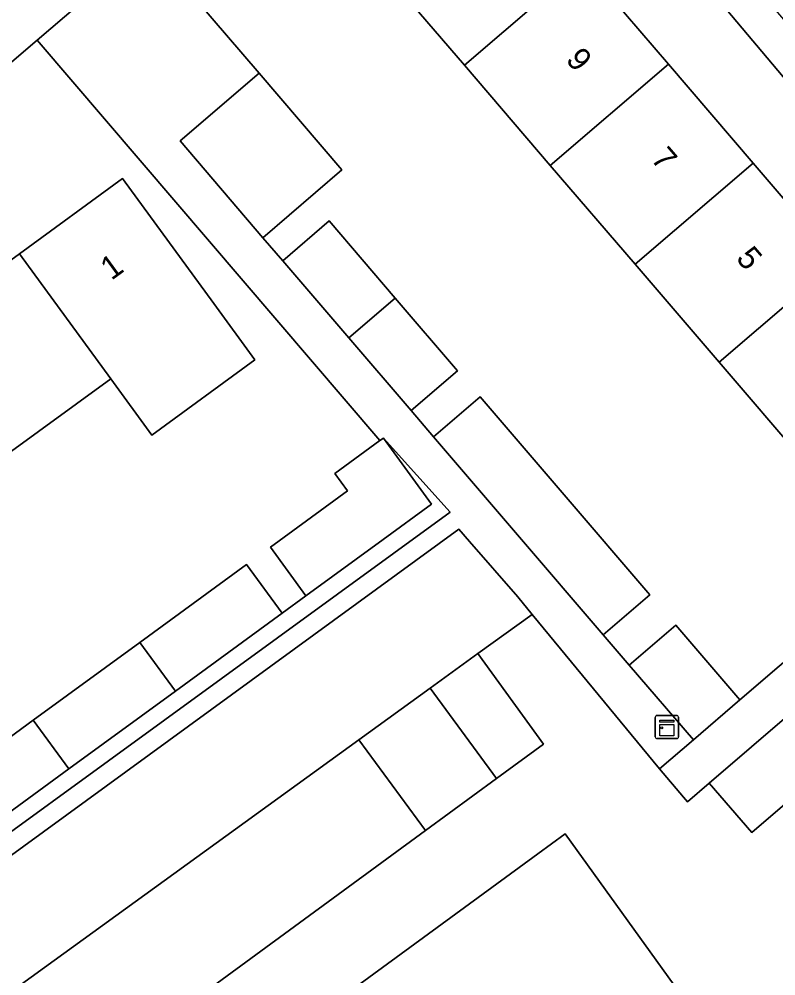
# Model space of a CAD drawing. Extents: x 159039 to 160102, y 381214 to 382524.
# Drawn here: x 159296.1 to 159328.7, y 381403.15 to 381444.39 of the extents above; entities that cross this region are included whole.
import ezdxf

# ---------------------------------------------------------------- set-up
doc = ezdxf.new("R2010")
doc.units = 0
for name, color, linetype in [('IMGEO_Erf', 7, 'Continuous'), ('IMGEO_Groenvoorziening', 7, 'Continuous'), ('IMGEO_Kast', 7, 'Continuous'), ('IMGEO_Pand', 7, 'Continuous'), ('IMGEO_Pand_nummerreeks', 7, 'Continuous'), ('IMGEO_Parkeervlak_halfverhard', 7, 'Continuous'), ('IMGEO_Parkeervlak_open', 7, 'Continuous'), ('IMGEO_Rijbaan_lokaal_halfverhard', 7, 'Continuous'), ('IMGEO_Rijbaan_lokaal_open', 7, 'Continuous'), ('IMGEO_Voetpad_open', 7, 'Continuous')]:
    doc.layers.add(name, color=color, linetype=linetype)

msp = doc.modelspace()

# ---------------------------------------------------------------- linework, layer by layer
at = {"layer": 'IMGEO_Erf'}
for points in [[(159313.561, 381454.682), (159312.01, 381456.432), (159309.4, 381454.198), (159301.691, 381447.601), (159306.439, 381442.052), (159310.009, 381437.884), (159306.602, 381434.965), (159307.456, 381433.968), (159309.461, 381435.686), (159312.306, 381432.365), (159314.99, 381429.232), (159312.985, 381427.514), (159313.954, 381426.383), (159315.959, 381428.101), (159319.576, 381423.877), (159323.265, 381419.571), (159321.261, 381417.854), (159322.385, 381416.542), (159324.389, 381418.259), (159327.147, 381415.04), (159333.82, 381420.762), (159329.941, 381425.29)], [(159329.941, 381425.29), (159326.252, 381429.596), (159322.634, 381433.82), (159318.981, 381438.084), (159315.282, 381442.402), (159311.688, 381446.598), (159316.78, 381450.96), (159320.374, 381446.765), (159324.073, 381442.447), (159327.725, 381438.182), (159331.344, 381433.958), (159335.033, 381429.652), (159338.909, 381425.126), (159341.458, 381427.312), (159335.852, 381433.782), (159319.724, 381452.954)], [(159293.47, 381411.804), (159296.711, 381414.169), (159301.301, 381417.519), (159305.896, 381420.873), (159307.426, 381418.777), (159308.458, 381419.53), (159306.928, 381421.626), (159310.249, 381424.05), (159309.701, 381424.801), (159311.645, 381426.22), (159296.875, 381443.481), (159263.262, 381414.719)]]:
    msp.add_lwpolyline(points, dxfattribs=at)
msp.add_lwpolyline([(159277.221, 381412.22), (159272.515, 381408.785), (159268.58, 381414.176), (159273.286, 381417.611), (159277.786, 381420.895), (159282.391, 381424.255), (159286.93, 381427.569), (159291.522, 381430.92), (159296.116, 381434.272), (159300.556, 381437.513), (159304.49, 381432.123), (159306.259, 381429.7), (159301.818, 381426.459), (159300.05, 381428.882), (159295.456, 381425.529), (159290.865, 381422.178), (159286.325, 381418.865), (159281.721, 381415.504)], close=True, dxfattribs=at)
at = {"layer": 'IMGEO_Groenvoorziening'}
for points in [[(159311.79, 381426.326), (159313.868, 381423.479), (159311.779, 381421.954), (159308.458, 381419.53), (159307.426, 381418.777), (159302.831, 381415.423), (159298.241, 381412.073), (159295, 381409.707), (159293.701, 381408.759), (159292.255, 381407.704), (159289.097, 381405.399), (159284.597, 381402.115), (159279.8, 381398.614), (159280.206, 381398.054), (159314.675, 381423.134)], [(159352.036, 381415.106), (159346.19, 381421.852), (159342.634, 381418.861), (159339.205, 381422.939), (159338.791, 381422.584), (159339.857, 381421.328), (159340.616, 381420.455), (159327.66, 381409.327), (159325.825, 381411.452), (159324.89, 381410.649), (159324.717, 381410.854), (159323.69, 381412.075), (159318.2, 381418.731), (159315.862, 381417.037), (159318.687, 381413.139), (159316.66, 381411.652), (159313.605, 381409.412), (159298.99, 381398.693), (159289.128, 381391.46), (159286.146, 381395.501), (159280.338, 381391.218), (159297.175, 381368.084)], [(159340.616, 381420.455), (159339.857, 381421.328), (159338.791, 381422.584), (159325.825, 381411.452), (159327.66, 381409.327)], [(159313.804, 381415.546), (159310.736, 381413.322), (159313.605, 381409.412), (159316.66, 381411.652)], [(159318.449, 381408.412), (159319.619, 381409.269), (159326.496, 381399.717), (159323.45, 381397.5), (159323.878, 381396.287), (159323.979, 381395.687), (159323.693, 381394.801), (159320.821, 381391.708), (159317.105, 381389.065), (159314.5, 381387.575), (159312.861, 381386.98), (159312, 381387.39), (159310.956, 381388.405), (159294.623, 381376.516), (159291.687, 381380.535), (159289.861, 381379.251), (159281.722, 381390.399), (159281.63, 381390.527), (159286.22, 381393.893), (159289.626, 381389.249), (159290.547, 381387.99)]]:
    msp.add_lwpolyline(points, close=True, dxfattribs=at)
at = {"layer": 'IMGEO_Kast'}
for p, q in [((159323.501, 381413.449), (159323.501, 381414.29)), ((159323.501, 381414.29), (159323.501, 381413.449)), ((159323.576, 381414.374), (159324.417, 381414.374)), ((159324.417, 381414.374), (159323.576, 381414.374)), ((159324.501, 381414.299), (159324.501, 381413.458)), ((159324.501, 381413.458), (159324.501, 381414.299)), ((159324.426, 381413.374), (159323.585, 381413.374)), ((159323.585, 381413.374), (159324.426, 381413.374))]:
    msp.add_line(p, q, dxfattribs=at)
for points in [[(159323.696, 381414.164), (159324.296, 381414.164), (159324.296, 381414.079), (159323.696, 381414.079), (159323.696, 381414.164)], [(159323.696, 381413.989), (159324.296, 381413.989), (159324.296, 381413.5), (159323.696, 381413.5), (159323.696, 381413.989)]]:
    msp.add_lwpolyline(points, dxfattribs=at)
msp.add_circle((159323.78, 381413.838), 0.0377, dxfattribs=at)
for centre, start, end in [((159323.579, 381414.296), 92.4484, 184.2845), ((159323.579, 381414.296), 92.4484, 184.2845), ((159324.423, 381414.296), 2.4484, 94.2845), ((159324.423, 381414.296), 2.4484, 94.2845), ((159323.579, 381413.452), 182.4484, 274.2845), ((159323.579, 381413.452), 182.4484, 274.2845), ((159324.423, 381413.452), 272.4484, 4.2845), ((159324.423, 381413.452), 272.4484, 4.2845)]:
    msp.add_arc(centre, 0.0779, start, end, dxfattribs=at)
at = {"layer": 'IMGEO_Pand'}
for points in [[(159320.374, 381446.765), (159316.78, 381450.96), (159311.688, 381446.598), (159315.282, 381442.402)], [(159320.374, 381446.765), (159315.282, 381442.402), (159318.981, 381438.084), (159324.073, 381442.447)], [(159322.634, 381433.82), (159327.725, 381438.182), (159324.073, 381442.447), (159318.981, 381438.084)], [(159310.009, 381437.884), (159306.439, 381442.052), (159303.032, 381439.133), (159306.602, 381434.965)], [(159331.344, 381433.958), (159327.725, 381438.182), (159322.634, 381433.82), (159326.252, 381429.596)], [(159300.05, 381428.882), (159301.818, 381426.459), (159306.259, 381429.7), (159304.49, 381432.123), (159300.556, 381437.513), (159296.116, 381434.272)], [(159309.461, 381435.686), (159307.456, 381433.968), (159310.301, 381430.647), (159312.306, 381432.365)], [(159300.05, 381428.882), (159296.116, 381434.272), (159291.522, 381430.92), (159295.456, 381425.529)], [(159331.344, 381433.958), (159326.252, 381429.596), (159329.941, 381425.29), (159335.033, 381429.652)], [(159312.306, 381432.365), (159310.301, 381430.647), (159312.985, 381427.514), (159314.99, 381429.232)], [(159315.959, 381428.101), (159313.954, 381426.383), (159317.572, 381422.16), (159321.261, 381417.854), (159323.265, 381419.571), (159319.576, 381423.877)], [(159311.779, 381421.954), (159313.868, 381423.479), (159311.79, 381426.326), (159311.645, 381426.22), (159309.701, 381424.801), (159310.249, 381424.05), (159306.928, 381421.626), (159308.458, 381419.53)], [(159301.301, 381417.519), (159302.831, 381415.423), (159307.426, 381418.777), (159305.896, 381420.873)], [(159324.389, 381418.259), (159322.385, 381416.542), (159325.143, 381413.322), (159327.147, 381415.04)], [(159296.711, 381414.169), (159298.241, 381412.073), (159302.831, 381415.423), (159301.301, 381417.519)], [(159298.241, 381412.073), (159296.711, 381414.169), (159293.47, 381411.804), (159295, 381409.707)], [(159323.45, 381397.5), (159326.496, 381399.717), (159319.619, 381409.269), (159318.449, 381408.412), (159290.547, 381387.99), (159289.626, 381389.249), (159286.22, 381393.893), (159281.63, 381390.527), (159281.722, 381390.399), (159289.861, 381379.251), (159291.687, 381380.535), (159294.623, 381376.516), (159310.956, 381388.405)]]:
    msp.add_lwpolyline(points, close=True, dxfattribs=at)
at = {"layer": 'IMGEO_Parkeervlak_halfverhard'}
msp.add_lwpolyline([(159315.862, 381417.037), (159313.804, 381415.546), (159316.66, 381411.652), (159318.687, 381413.139)], close=True, dxfattribs=at)
at = {"layer": 'IMGEO_Parkeervlak_open'}
msp.add_lwpolyline([(159313.605, 381409.412), (159310.736, 381413.322), (159286.146, 381395.501), (159289.128, 381391.46), (159298.99, 381398.693)], close=True, dxfattribs=at)
at = {"layer": 'IMGEO_Rijbaan_lokaal_halfverhard'}
msp.add_lwpolyline([(159310.736, 381413.322), (159313.804, 381415.546), (159315.862, 381417.037), (159318.2, 381418.731), (159317.581, 381419.482), (159315.506, 381421.872), (159315.041, 381422.408), (159277.551, 381395.074), (159280.338, 381391.218), (159286.146, 381395.501)], close=True, dxfattribs=at)
at = {"layer": 'IMGEO_Rijbaan_lokaal_open'}
for points in [[(159296.875, 381443.481), (159301.688, 381447.599), (159301.691, 381447.601), (159309.4, 381454.198), (159312.01, 381456.432), (159309.567, 381459.253)], [(159309.494, 381458.306), (159309.289, 381458.131), (159308.398, 381457.371), (159294.831, 381445.789), (159294.662, 381445.645), (159293.7, 381444.812), (159280.226, 381433.226), (159279.48, 381432.596), (159276.058, 381429.872), (159261.321, 381417.145), (159263.262, 381414.719), (159296.875, 381443.481)]]:
    msp.add_lwpolyline(points, dxfattribs=at)
at = {"layer": 'IMGEO_Voetpad_open'}
for points in [[(159319.724, 381452.954), (159335.852, 381433.782), (159341.458, 381427.312), (159346.19, 381421.852), (159352.036, 381415.106), (159352.5, 381416.855), (159341.136, 381429.955), (159340.657, 381430.507), (159333.778, 381438.529), (159329.812, 381443.465), (159320.759, 381454.056)], [(159277.551, 381395.074), (159315.041, 381422.408), (159315.506, 381421.872), (159317.581, 381419.482), (159318.2, 381418.731), (159323.69, 381412.075), (159325.143, 381413.322), (159322.385, 381416.542), (159321.261, 381417.854), (159317.572, 381422.16), (159313.954, 381426.383), (159312.985, 381427.514), (159310.301, 381430.647), (159307.456, 381433.968), (159306.602, 381434.965), (159303.032, 381439.133), (159306.439, 381442.052), (159301.691, 381447.601), (159301.688, 381447.599), (159296.875, 381443.481), (159311.645, 381426.22), (159311.79, 381426.326), (159314.675, 381423.134), (159280.206, 381398.054)]]:
    msp.add_lwpolyline(points, dxfattribs=at)
msp.add_lwpolyline([(159341.458, 381427.312), (159338.909, 381425.126), (159333.82, 381420.762), (159327.147, 381415.04), (159325.143, 381413.322), (159323.69, 381412.075), (159324.717, 381410.854), (159324.89, 381410.649), (159325.825, 381411.452), (159338.791, 381422.584), (159339.205, 381422.939), (159342.634, 381418.861), (159346.19, 381421.852)], close=True, dxfattribs=at)

# ---------------------------------------------------------------- texts
at = {"layer": 'IMGEO_Pand_nummerreeks'}
for s, rotation, p in [('9', 310.5838, (159319.61, 381442.614)), ('7', 310.5838, (159323.277, 381438.333)), ('5', 310.5838, (159326.945, 381434.052)), ('1', 36.123, (159300.076, 381433.102))]:
    msp.add_text(s, height=1, rotation=rotation, dxfattribs=at).set_placement(p)

doc.saveas('drawing.dxf')
